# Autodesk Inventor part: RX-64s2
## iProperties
Created: 2009-01
Part Number: RX-64s2
Material: Aluminum-6061
Document SubType Name: Sheet Metal
Designer: Administrator
Density: 1 g/cm^3
Author: Administrator
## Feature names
1. Hole1
2. Hole2
3. Corner Round1
4. Plate1
5. Plate2
6. Bend1
7. Cut1
8. Cut2
